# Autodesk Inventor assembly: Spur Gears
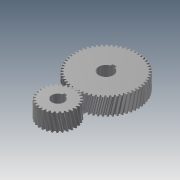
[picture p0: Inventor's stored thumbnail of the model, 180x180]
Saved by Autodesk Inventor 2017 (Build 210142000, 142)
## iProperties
ClientObjectVersion: 1
Created: 2019-03
Part Number: Spur Gears
Document SubType Name: Assembly
Designer: user
Categories: <?xml version="1.0" encoding="UTF-16"?> <MemberInstance><Categories><FamilyTemplate/><ParamToTemplateMap><ParamToTemplate><ParamToTemplate CategoryParameter="//
Author: user
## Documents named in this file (3)
- C:\Users\user\Documents\EIA\Cursos\Diseño asistido por computador\Clase 7 Dynamic simulation\Ensamble reductor de velocidad\Ensamble\Design Accelerator\Spur Gears1.iam
- C:\Users\user\Documents\EIA\Cursos\Diseño asistido por computador\Clase 7 Dynamic simulation\Ensamble reductor de velocidad\Ensamble\Design Accelerator\Spur Gear11.ipt
- C:\Users\user\Documents\EIA\Cursos\Diseño asistido por computador\Clase 7 Dynamic simulation\Ensamble reductor de velocidad\Ensamble\Design Accelerator\Spur Gear21.ipt
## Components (2 placed, 2 different names)
1. Spur Gear1:1 — Rotation:1
2. Spur Gear2:1 — Rotation:1
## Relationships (1: RelateRotation 1)
- Rotation:1 [RelateRotation]: Spur Gear1:1 ↔ Spur Gear2:1
